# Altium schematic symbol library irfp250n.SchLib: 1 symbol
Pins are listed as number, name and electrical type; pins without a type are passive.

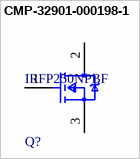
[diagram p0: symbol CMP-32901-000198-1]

## CMP-32901-000198-1
designator Q?, comment IRFP250NPBF
MOSFET N-CH 200V 30A TO-247AC; Rds On Max: 75mR; Input Capacitance: 2.159nF; Turn-Off Delay Time: 41ns; Max Power Dissipation: 214W; Turn-On Delay Time: 14ns; Gate to Source Voltage (Vgs): 20V; Element Configuration: Single
footprint FP-PG-TO247-3-MFG
pins: 1 GATE, 2 DRAIN, 3 SOURCE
